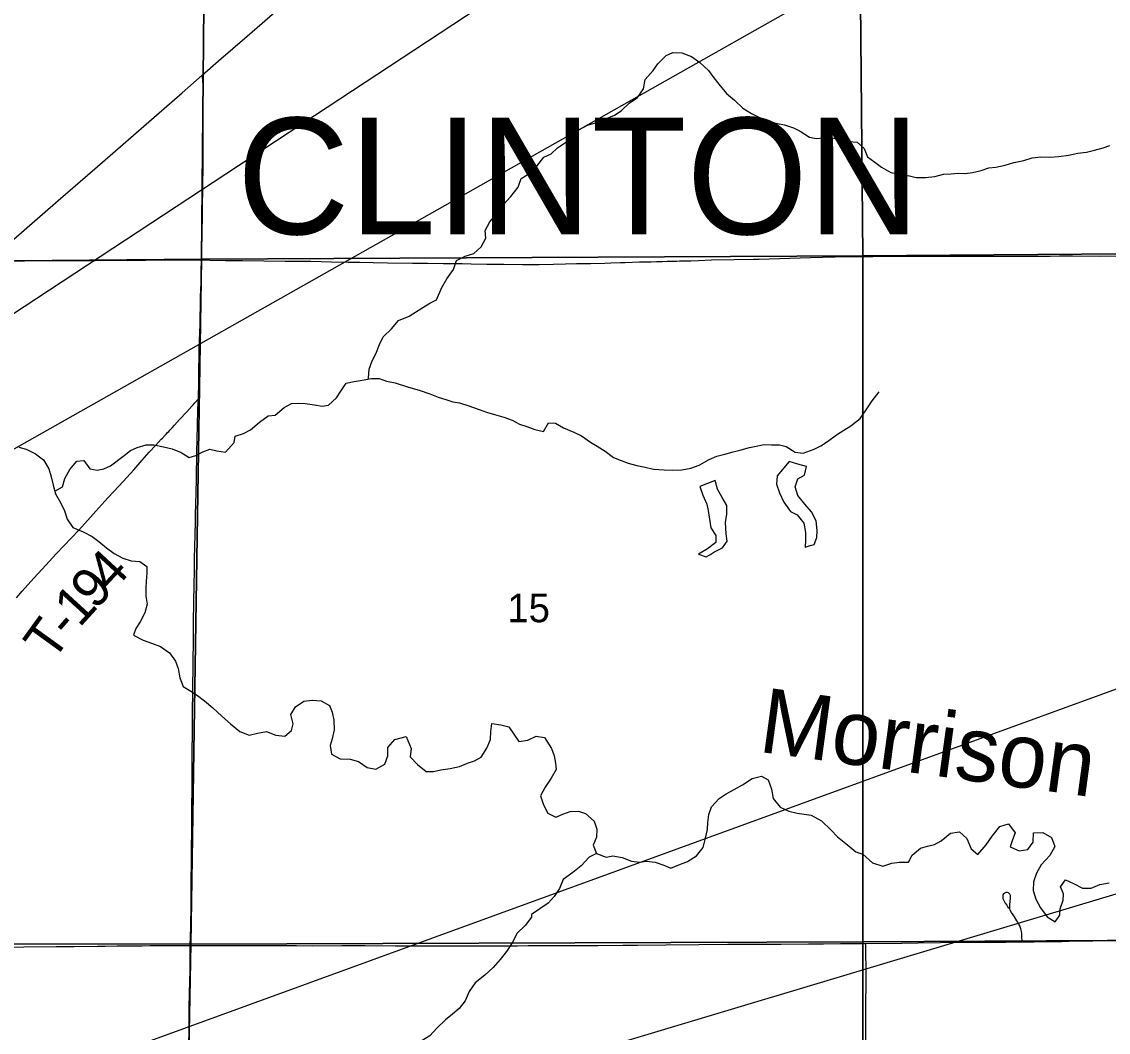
# Model space of a CAD drawing. Extents: x 0 to 34, y 0 to 22.
# Drawn here: x 6.886 to 7.681, y 18.856 to 19.597 of the extents above; entities that cross this region are included whole.
import ezdxf

# ---------------------------------------------------------------- set-up
doc = ezdxf.new("R2010")
doc.units = 0
for name, color, linetype in [('GM_X_Minor_Lake', 7, 'Continuous'), ('GM_X_Minor_River', 7, 'Continuous'), ('GM_X_Minor_River_Text', 7, 'Continuous'), ('GM_X_Section', 7, 'Continuous'), ('GM_X_Section_Text', 7, 'Continuous'), ('GM_X_State_Route', 7, 'Continuous'), ('GM_X_Township_Road', 7, 'Continuous'), ('GM_X_Township_Road_Text', 7, 'Continuous'), ('GM_X_Township_Text', 7, 'Continuous'), ('SH_Text', 7, 'Continuous')]:
    doc.layers.add(name, color=color, linetype=linetype)

msp = doc.modelspace()

# ---------------------------------------------------------------- linework, layer by layer
at = {"layer": 'GM_X_Minor_Lake'}
for points in [[(7.44728, 19.27438), (7.43871, 19.264), (7.43811, 19.25775), (7.44034, 19.25148), (7.44352, 19.24463), (7.4484, 19.23797), (7.4533, 19.23529), (7.45818, 19.22938), (7.45947, 19.22255), (7.45943, 19.21686), (7.45921, 19.21174), (7.46288, 19.21291)], [(7.46288, 19.21291), (7.46566, 19.21379), (7.46777, 19.2189), (7.4678, 19.22383), (7.46727, 19.23104), (7.46371, 19.2375), (7.45883, 19.24322), (7.45376, 19.2495), (7.45171, 19.25596), (7.45383, 19.26183), (7.45857, 19.26446), (7.46012, 19.27071), (7.4537, 19.27245), (7.44728, 19.27438)], [(7.38922, 19.20618), (7.39223, 19.20813), (7.39849, 19.21113), (7.40193, 19.21623), (7.40139, 19.22154), (7.40068, 19.22989), (7.40166, 19.23595), (7.4017, 19.24221), (7.39833, 19.24811), (7.39496, 19.25419), (7.39329, 19.26046), (7.38211, 19.25616)], [(7.38211, 19.25616), (7.38415, 19.2497), (7.38714, 19.24324), (7.38806, 19.23849), (7.38897, 19.23223), (7.39006, 19.22578), (7.39363, 19.22026), (7.3936, 19.21514), (7.38752, 19.21062), (7.38106, 19.20649), (7.38672, 19.20456), (7.38922, 19.20618)]]:
    msp.add_lwpolyline(points, dxfattribs=at)
at = {"layer": 'GM_X_Minor_River'}
for points in [[(7.16914, 19.3808), (7.17914, 19.38719), (7.18445, 19.39038), (7.18919, 19.39282), (7.19303, 19.4019), (7.19685, 19.40814), (7.20162, 19.41513), (7.20393, 19.42156), (7.21019, 19.42475), (7.21663, 19.4268), (7.22195, 19.4317), (7.22521, 19.43794), (7.22486, 19.44363), (7.2283, 19.44987), (7.23306, 19.45553), (7.23802, 19.46233), (7.24354, 19.46856), (7.24888, 19.47535), (7.25119, 19.4816), (7.25745, 19.48555), (7.26278, 19.49083), (7.26773, 19.49725), (7.27304, 19.49987), (7.2778, 19.50421), (7.28502, 19.5091), (7.28976, 19.5121), (7.29339, 19.51739), (7.29984, 19.52077), (7.30647, 19.52263), (7.31254, 19.52506), (7.31955, 19.52806), (7.32449, 19.53125), (7.3302, 19.53691), (7.33646, 19.54105), (7.34066, 19.54747), (7.34203, 19.55429), (7.34774, 19.5607), (7.35117, 19.5658), (7.35745, 19.57184), (7.36219, 19.5739), (7.36881, 19.57367), (7.37598, 19.57098), (7.38201, 19.56658), (7.38822, 19.56086), (7.39216, 19.55553), (7.39592, 19.55076), (7.40155, 19.54391), (7.40739, 19.53913), (7.41341, 19.53322), (7.41981, 19.5292), (7.42566, 19.52633), (7.43132, 19.52383), (7.43756, 19.52228), (7.44398, 19.5211), (7.45059, 19.51879), (7.45549, 19.5163), (7.46228, 19.51209), (7.46719, 19.51111), (7.47287, 19.51146), (7.47778, 19.51143), (7.48383, 19.51083), (7.49101, 19.50889), (7.49725, 19.50829), (7.50233, 19.50371), (7.50475, 19.49763), (7.51003, 19.49362), (7.51511, 19.48999), (7.5219, 19.48616), (7.52833, 19.48479), (7.53551, 19.48362), (7.54042, 19.48245), (7.54723, 19.48241), (7.55404, 19.48313), (7.5603, 19.48499), (7.56597, 19.48515), (7.57089, 19.4855), (7.57619, 19.48547), (7.58168, 19.48601), (7.58793, 19.48769), (7.59362, 19.48955), (7.59873, 19.49009), (7.60554, 19.49157), (7.61199, 19.49343), (7.61918, 19.49491), (7.62525, 19.49696), (7.63168, 19.49768), (7.6383, 19.49745), (7.64493, 19.4978), (7.65193, 19.49871), (7.65875, 19.50018), (7.66518, 19.5011), (7.67087, 19.50239), (7.67731, 19.50406), (7.68224, 19.50593)], [(7.13907, 19.33485), (7.13946, 19.33574), (7.13988, 19.34219), (7.142, 19.34826), (7.14488, 19.35337), (7.14757, 19.36018), (7.15026, 19.36586), (7.15616, 19.37152), (7.16151, 19.37776), (7.16914, 19.3808)], [(6.90975, 19.25273), (6.91548, 19.25581), (6.91703, 19.26207), (6.92067, 19.2685), (6.92601, 19.27473), (6.93094, 19.27508), (6.93545, 19.26898), (6.94074, 19.268), (6.94567, 19.26911), (6.95061, 19.27136), (6.96051, 19.2789), (6.96527, 19.28247), (6.97001, 19.28472), (6.97665, 19.28658), (6.98234, 19.28674), (6.98934, 19.28518), (6.99558, 19.28381), (7.00219, 19.28112), (7.00823, 19.27747), (7.01297, 19.27878), (7.0181, 19.28159), (7.02323, 19.28346), (7.02833, 19.28229), (7.03477, 19.28131), (7.04106, 19.28829), (7.04185, 19.29303), (7.04792, 19.2949), (7.05305, 19.29771), (7.05953, 19.30337), (7.06599, 19.30789), (7.07111, 19.30843), (7.07759, 19.31409), (7.08309, 19.3169), (7.08783, 19.31725), (7.09313, 19.31703), (7.09995, 19.31585), (7.10543, 19.31487), (7.11017, 19.3156), (7.11608, 19.32107), (7.11914, 19.32599), (7.12296, 19.33185), (7.12884, 19.33315), (7.13491, 19.33406), (7.14173, 19.33535), (7.14723, 19.33513), (7.15252, 19.33339), (7.15895, 19.33202), (7.16879, 19.32899)], [(7.16879, 19.32899), (7.17652, 19.32671), (7.18426, 19.32401), (7.19048, 19.3217), (7.19596, 19.31978), (7.20125, 19.31823), (7.20616, 19.31744), (7.21296, 19.31532), (7.22051, 19.31262), (7.22579, 19.31051), (7.23165, 19.30877), (7.23845, 19.30702), (7.24468, 19.30471), (7.24996, 19.30184), (7.25524, 19.3001), (7.26109, 19.2978), (7.26752, 19.29643), (7.27115, 19.30267), (7.27644, 19.30245), (7.28229, 19.2992), (7.28965, 19.29593), (7.2953, 19.29324), (7.3019, 19.28866), (7.3068, 19.28559), (7.31264, 19.28196), (7.31867, 19.27737), (7.32452, 19.27526), (7.32962, 19.27314), (7.33585, 19.27159), (7.3419, 19.27023), (7.34813, 19.26887), (7.35588, 19.26826), (7.36231, 19.26803), (7.36893, 19.26837), (7.37537, 19.26947), (7.38144, 19.2719), (7.38884, 19.27603), (7.39453, 19.27847), (7.40021, 19.27976), (7.40646, 19.28163), (7.41234, 19.28311), (7.4184, 19.28478), (7.42332, 19.2857), (7.4292, 19.287), (7.43449, 19.28678), (7.44035, 19.28656), (7.44527, 19.28539), (7.45167, 19.28137), (7.45753, 19.28058), (7.46568, 19.28357), (7.47062, 19.28582), (7.47555, 19.28921), (7.48201, 19.29391), (7.48733, 19.29748), (7.49246, 19.30068), (7.49948, 19.30595), (7.50368, 19.31237), (7.50807, 19.31879), (7.51322, 19.3254)], [(6.88346, 19.28485), (6.88875, 19.28349), (6.89555, 19.28004), (6.9014, 19.27564), (6.90552, 19.26916), (6.907, 19.26326), (6.90848, 19.25718), (6.91033, 19.25071), (6.91389, 19.24443), (6.91688, 19.23834), (6.91893, 19.23225), (6.92306, 19.22615), (6.93042, 19.22288), (6.93703, 19.21942), (6.94193, 19.21598), (6.94759, 19.2112), (6.95324, 19.20699), (6.95966, 19.20372), (6.96571, 19.20179), (6.97196, 19.20118), (6.97705, 19.19755), (6.97721, 19.1928), (6.9766, 19.18692), (6.97638, 19.18198), (6.97634, 19.17591), (6.97744, 19.17002), (6.9757, 19.16357), (6.97225, 19.15714), (6.969, 19.15222), (6.96745, 19.1473), (6.97444, 19.14365), (6.98048, 19.14133), (6.9871, 19.13902), (6.9937, 19.13442), (6.99802, 19.12813), (7.00007, 19.12299), (7.00135, 19.11615), (7.00377, 19.10968), (7.00943, 19.10623), (7.01434, 19.10298), (7.01943, 19.09915), (7.02546, 19.09399), (7.03205, 19.08787), (7.03845, 19.08233), (7.04523, 19.07679), (7.05204, 19.07409), (7.05811, 19.07557), (7.06474, 19.07667), (7.07155, 19.07416)], [(7.07155, 19.07416), (7.07817, 19.07337), (7.08312, 19.07751), (7.08429, 19.08244), (7.08262, 19.08929), (7.08588, 19.09477), (7.09215, 19.09891), (7.09822, 19.09963), (7.10466, 19.09922), (7.11088, 19.09576), (7.11275, 19.09082), (7.11404, 19.08511), (7.11437, 19.0779), (7.11282, 19.07145), (7.11127, 19.06653), (7.11237, 19.06006), (7.11879, 19.0568), (7.12598, 19.05657), (7.13222, 19.05482), (7.13844, 19.05042), (7.14488, 19.04924), (7.15134, 19.05281), (7.15365, 19.05887), (7.15369, 19.06514), (7.15862, 19.07085), (7.16703, 19.07301)], [(7.16703, 19.07301), (7.17065, 19.0643), (7.16986, 19.05824), (7.17531, 19.05252), (7.18171, 19.04755), (7.18701, 19.04733), (7.19231, 19.04863), (7.19913, 19.04954), (7.20595, 19.05121), (7.21201, 19.05364), (7.21713, 19.05532), (7.22187, 19.05795), (7.22607, 19.06456), (7.22876, 19.07099), (7.22898, 19.07668), (7.22977, 19.08256), (7.2362, 19.08157), (7.24224, 19.08021), (7.24637, 19.07412), (7.24956, 19.06936), (7.25599, 19.07027), (7.26207, 19.07327), (7.2683, 19.07229), (7.27336, 19.0643), (7.27541, 19.05898), (7.27633, 19.05366), (7.27687, 19.04892), (7.27324, 19.04268), (7.26866, 19.03607), (7.26541, 19.02964), (7.26745, 19.02299), (7.27082, 19.01691), (7.27667, 19.01403), (7.28179, 19.01628), (7.28709, 19.01814), (7.29315, 19.01849), (7.29825, 19.01675), (7.30464, 19.01103), (7.30669, 19.00533), (7.30628, 18.99926), (7.30379, 18.9934), (7.3064, 18.98732), (7.31338, 18.98462), (7.31831, 18.98573), (7.32511, 18.98456), (7.3319, 18.98187), (7.33814, 18.98107), (7.34306, 18.9818), (7.3493, 18.98101), (7.35572, 18.97889), (7.36082, 18.97677), (7.36669, 18.97902), (7.37295, 18.98145), (7.3796, 18.98577), (7.38436, 18.99181), (7.3861, 18.99863), (7.38765, 19.00488), (7.38787, 19.01), (7.38866, 19.01606), (7.39058, 19.02155), (7.39611, 19.02759), (7.40123, 19.03116), (7.40711, 19.03416), (7.41319, 19.03773), (7.42021, 19.04243), (7.42703, 19.0441), (7.43194, 19.04142), (7.43436, 19.03439), (7.43564, 19.02755), (7.44071, 19.02127), (7.44713, 19.01839), (7.45336, 19.01703), (7.45846, 19.01624), (7.46338, 19.01545), (7.47111, 19.01124), (7.47807, 19.00437), (7.48277, 18.99961), (7.48898, 18.99464), (7.49632, 18.98853), (7.50123, 18.98699), (7.50838, 18.9805), (7.51594, 18.97818), (7.52257, 18.98042), (7.52787, 18.98115), (7.53468, 18.98111), (7.53736, 18.98622), (7.54363, 18.9913), (7.54856, 18.99279), (7.55386, 18.9939), (7.55879, 18.99672), (7.56545, 19.00218), (7.57207, 19.00328), (7.57753, 18.99832), (7.5807, 18.99072), (7.5856, 18.98671), (7.5915, 18.99369), (7.59589, 19.00011), (7.6016, 19.0071), (7.60805, 19.00915), (7.61293, 19.00248), (7.61101, 18.99737)], [(7.61101, 18.99737), (7.60927, 18.99226), (7.61569, 18.98938), (7.62213, 18.9903), (7.62613, 18.99577), (7.62617, 19.00241), (7.63317, 19.00275), (7.63939, 18.99911), (7.642, 18.99246), (7.63818, 18.98584), (7.6319, 18.97905), (7.62846, 18.973), (7.62615, 18.96676), (7.62611, 18.96031), (7.62797, 18.95404), (7.63134, 18.94758), (7.63622, 18.9411), (7.64206, 18.93728), (7.64549, 18.94219), (7.6459, 18.94693), (7.64802, 18.95317), (7.64823, 18.95791), (7.64599, 18.96305), (7.6498, 18.96814), (7.65565, 18.96546), (7.66206, 18.96201), (7.6685, 18.96197), (7.67475, 18.96478), (7.68176, 18.96588)], [(7.3064, 18.98732), (7.30109, 18.98469), (7.29519, 18.97847), (7.28892, 18.97357), (7.28189, 18.9683), (7.2792, 18.96187), (7.27539, 18.95601), (7.27101, 18.95111), (7.25884, 18.94281)], [(7.25884, 18.94281), (7.25882, 18.94088), (7.25405, 18.93463), (7.24834, 18.92896), (7.2447, 18.92196), (7.2405, 18.91571), (7.23592, 18.90985), (7.23058, 18.9038), (7.22448, 18.89832), (7.21763, 18.89265), (7.21323, 18.88622), (7.21017, 18.87959), (7.20578, 18.87391), (7.20102, 18.86976), (7.19588, 18.86561), (7.1894, 18.85956), (7.18425, 18.85389), (7.17797, 18.84993), (7.17225, 18.84388), (7.16541, 18.83679)]]:
    msp.add_lwpolyline(points, dxfattribs=at)
at = {"layer": 'GM_X_Section'}
for points in [[(6.53817, 19.93156), (7.02187, 19.92598), (7.01728, 19.42257), (6.52479, 19.41836)], [(7.02187, 19.92598), (7.4966, 19.92992), (7.50144, 19.42512), (7.01728, 19.42257)], [(7.4966, 19.92992), (7.96613, 19.92967), (7.98141, 19.42878), (7.50144, 19.42512)], [(7.50144, 19.42512), (7.50124, 18.92259), (7.00934, 18.92111), (7.01728, 19.42257)], [(7.50144, 19.42512), (7.98141, 19.42878), (7.99306, 18.92551), (7.50124, 18.92259)], [(7.01728, 19.42257), (7.00934, 18.92111), (6.51159, 18.92185), (6.52479, 19.41836)], [(7.99306, 18.92551), (7.99816, 18.41923), (7.50153, 18.41698), (7.50124, 18.92259)], [(7.00934, 18.92111), (6.99984, 18.41775), (6.50305, 18.41943), (6.51159, 18.92185)], [(7.50124, 18.92259), (7.50153, 18.41698), (6.99984, 18.41775), (7.00934, 18.92111)]]:
    msp.add_lwpolyline(points, close=True, dxfattribs=at)
at = {"layer": 'GM_X_State_Route'}
for points in [[(6.86621, 19.42565), (6.91225, 19.46555), (6.93904, 19.48874), (6.98618, 19.52975), (7.00311, 19.54438), (7.01772, 19.55727), (7.02968, 19.56783), (7.05049, 19.58605), (7.0745, 19.60676)], [(7.52955, 18.92178), (7.52999, 18.92178), (7.54179, 18.9219), (7.55826, 18.92224), (7.57381, 18.92235), (7.58778, 18.92242), (7.60611, 18.92258), (7.60735, 18.9226), (7.61263, 18.92261), (7.61798, 18.92267), (7.62661, 18.92276), (7.63531, 18.92289), (7.64711, 18.92305), (7.6524, 18.92313), (7.6698, 18.92343), (7.69156, 18.92364)], [(6.85756, 18.91859), (6.88709, 18.91894), (6.9107, 18.91923), (6.92407, 18.91935), (6.94115, 18.91959), (6.94675, 18.91965), (6.95545, 18.91974), (6.96353, 18.91977), (6.97378, 18.91983), (6.97968, 18.9199), (6.99163, 18.92), (7.00051, 18.91998), (7.00897, 18.91996), (7.01045, 18.91995), (7.02413, 18.92006), (7.03501, 18.92008), (7.04309, 18.92003), (7.07137, 18.92001), (7.07821, 18.91997), (7.0866, 18.91993), (7.09809, 18.91989), (7.11985, 18.91999), (7.13695, 18.91994), (7.15901, 18.91989), (7.17642, 18.91988), (7.18605, 18.91982), (7.19475, 18.91979), (7.19754, 18.91979), (7.21555, 18.91978), (7.2199, 18.9198), (7.22735, 18.91986), (7.23885, 18.91984), (7.24227, 18.91984), (7.24848, 18.91989), (7.25625, 18.91992), (7.26495, 18.91997), (7.26961, 18.92001), (7.27521, 18.92002), (7.27863, 18.92002), (7.28546, 18.92), (7.28732, 18.92), (7.29725, 18.92006), (7.3075, 18.92012), (7.32551, 18.92026), (7.33639, 18.92036), (7.35721, 18.9205), (7.38114, 18.92072), (7.40258, 18.92094), (7.41875, 18.92109), (7.44143, 18.92105), (7.46163, 18.92126), (7.47251, 18.92136), (7.48494, 18.92141), (7.48712, 18.92142), (7.4924, 18.92143), (7.50357, 18.92153), (7.52955, 18.92178)]]:
    msp.add_lwpolyline(points, dxfattribs=at)
at = {"layer": 'GM_X_Township_Road'}
for points in [[(7.01715, 19.42204), (7.01721, 19.42384), (7.01725, 19.42694), (7.01737, 19.43004), (7.01745, 19.43346), (7.01754, 19.43749), (7.01761, 19.44153), (7.01769, 19.44526), (7.01779, 19.45116), (7.01786, 19.45396), (7.01791, 19.45924), (7.01802, 19.46452), (7.0181, 19.47042), (7.01825, 19.47943), (7.01838, 19.48751), (7.01844, 19.49435), (7.01848, 19.50149), (7.01846, 19.5136), (7.01843, 19.51827), (7.0184, 19.52324), (7.01837, 19.53194), (7.01838, 19.53816), (7.01837, 19.54406), (7.01831, 19.55057), (7.0182, 19.55302), (7.01811, 19.5539), (7.01772, 19.55727)], [(7.01715, 19.42204), (7.02317, 19.42191), (7.03467, 19.42176), (7.0471, 19.42163), (7.07849, 19.42125), (7.09714, 19.42108), (7.11236, 19.4208), (7.12448, 19.42055), (7.13318, 19.42036), (7.14281, 19.42013), (7.15337, 19.41999), (7.1717, 19.41981), (7.18258, 19.41962), (7.19437, 19.4195), (7.20248, 19.41939), (7.20806, 19.41941), (7.21458, 19.41932), (7.22606, 19.41909), (7.23849, 19.41888), (7.25217, 19.41872), (7.2643, 19.41885), (7.27486, 19.41898), (7.28357, 19.41913), (7.29164, 19.41937), (7.30189, 19.41954), (7.31246, 19.41978), (7.31681, 19.41996), (7.32395, 19.4202), (7.32736, 19.4203), (7.3379, 19.42062), (7.34225, 19.42072), (7.34628, 19.4208), (7.35032, 19.42088), (7.35436, 19.42098), (7.35808, 19.42108), (7.36149, 19.42118), (7.36521, 19.42129), (7.36706, 19.42134), (7.36954, 19.42141), (7.3717, 19.42145), (7.37541, 19.42152), (7.38099, 19.42175), (7.3906, 19.42207), (7.40707, 19.42243), (7.42136, 19.42269), (7.4254, 19.42275), (7.43286, 19.42293), (7.44032, 19.42316), (7.463, 19.42376), (7.47169, 19.42402), (7.48101, 19.42425), (7.49126, 19.42451), (7.50089, 19.42464), (7.50524, 19.42468), (7.50866, 19.42471), (7.51301, 19.42475), (7.52016, 19.42483), (7.52699, 19.42489), (7.53228, 19.42491), (7.53663, 19.4249), (7.55527, 19.4249), (7.56024, 19.42488), (7.56553, 19.42485), (7.57672, 19.42482), (7.59008, 19.42483), (7.59972, 19.42485), (7.60562, 19.42486), (7.61059, 19.42489), (7.61463, 19.4249), (7.61991, 19.42492), (7.62768, 19.42495), (7.63856, 19.42494), (7.64539, 19.42498), (7.64943, 19.42499), (7.65471, 19.425), (7.6746, 19.42492), (7.69543, 19.42502)], [(6.86138, 19.42139), (6.87402, 19.42147), (6.8877, 19.42152), (6.89857, 19.42162), (6.90789, 19.42169), (6.92467, 19.42177), (6.92746, 19.42174), (6.92995, 19.42175), (6.93927, 19.42178), (6.95481, 19.42184), (6.96787, 19.42188), (6.97626, 19.42198), (6.99086, 19.42216), (6.99987, 19.42217), (7.00981, 19.42216), (7.01602, 19.42207), (7.01715, 19.42204)], [(7.01488, 19.32025), (7.0151, 19.33308), (7.01512, 19.33396), (7.01514, 19.33547), (7.01521, 19.34009), (7.01527, 19.3438), (7.01541, 19.34908), (7.01548, 19.35218), (7.01557, 19.35653), (7.01591, 19.36895), (7.01609, 19.37485), (7.01619, 19.3795), (7.01625, 19.38229), (7.01628, 19.38322), (7.01634, 19.38538), (7.01637, 19.38755), (7.01642, 19.39003), (7.01645, 19.39189), (7.01647, 19.39375), (7.01652, 19.39623), (7.0166, 19.39902), (7.01681, 19.40679), (7.01689, 19.41144), (7.01701, 19.41672), (7.01707, 19.4192), (7.01713, 19.42168), (7.01715, 19.42204)], [(6.88164, 19.17457), (6.88585, 19.17954), (6.89433, 19.18904), (6.9005, 19.1956), (6.91084, 19.20687), (6.92197, 19.21849), (6.92714, 19.224), (6.93397, 19.2315), (6.93976, 19.238), (6.94643, 19.24537), (6.94896, 19.24811), (6.9566, 19.25633), (6.96254, 19.26278), (6.96761, 19.26845), (6.97366, 19.27534), (6.97895, 19.28123), (6.9837, 19.28638), (6.98773, 19.2908), (6.98854, 19.29161), (6.99067, 19.29382), (6.99131, 19.29449), (6.99238, 19.2956), (6.99322, 19.29651), (6.99409, 19.29739), (6.99491, 19.29831), (6.99577, 19.29922), (6.99742, 19.30106), (7.00111, 19.30523), (7.00633, 19.31093), (7.0101, 19.31499), (7.01111, 19.31607), (7.0124, 19.3175), (7.01488, 19.32025)], [(7.00897, 18.91996), (7.00929, 18.93358), (7.00939, 18.93914), (7.0095, 18.9444), (7.00952, 18.94718), (7.00955, 18.94873), (7.00955, 18.95182), (7.00958, 18.95337), (7.00958, 18.95615), (7.0096, 18.95832), (7.00963, 18.96173), (7.00972, 18.97134), (7.00978, 18.97724), (7.00979, 18.97942), (7.00988, 18.9909), (7.00993, 18.9968), (7.00997, 18.99804), (7.00997, 19.00207), (7.01004, 19.00455), (7.01006, 19.00889), (7.01012, 19.01075), (7.01011, 19.0154), (7.01015, 19.01695), (7.01014, 19.01974), (7.01019, 19.02253), (7.0102, 19.02346), (7.01021, 19.02686), (7.01026, 19.02934), (7.01023, 19.03212), (7.0104, 19.03767), (7.01043, 19.04383), (7.0104, 19.04754), (7.01037, 19.0559), (7.01042, 19.06459), (7.01047, 19.07298), (7.01057, 19.08417), (7.01066, 19.09349), (7.01077, 19.10312), (7.01092, 19.1143), (7.011, 19.11895), (7.01117, 19.13071), (7.0112, 19.14025), (7.01128, 19.14652), (7.01136, 19.15553), (7.01161, 19.17232), (7.01199, 19.19469), (7.01215, 19.20308), (7.01253, 19.22111), (7.01273, 19.23011), (7.01285, 19.23632), (7.01294, 19.24258), (7.01321, 19.25255), (7.01343, 19.26075), (7.01349, 19.26769), (7.0137, 19.2754), (7.01387, 19.28174), (7.01408, 19.29066), (7.0146, 19.31174), (7.01484, 19.31794), (7.01488, 19.32025)], [(7.61798, 18.92267), (7.61783, 18.92708), (7.6178, 18.92794), (7.61767, 18.92888), (7.61747, 18.93019), (7.61696, 18.93218), (7.61616, 18.93437), (7.61553, 18.93573), (7.61474, 18.93709), (7.61401, 18.93819), (7.6123, 18.94093), (7.61128, 18.94245), (7.61017, 18.94429), (7.60912, 18.94596), (7.6089, 18.94697), (7.60886, 18.94786), (7.60898, 18.9498), (7.60941, 18.95501), (7.60946, 18.9556), (7.60943, 18.95626), (7.60935, 18.9567), (7.60921, 18.95716), (7.60893, 18.95769), (7.60853, 18.95815), (7.60803, 18.9585), (7.60715, 18.9588), (7.60653, 18.95883), (7.60592, 18.95874), (7.60507, 18.95837), (7.6047, 18.95811), (7.60438, 18.95776), (7.60392, 18.95711), (7.60376, 18.95654), (7.60372, 18.95609), (7.60374, 18.95548), (7.60392, 18.95456), (7.60436, 18.95339), (7.60564, 18.9511), (7.60664, 18.94948), (7.60759, 18.94813), (7.6085, 18.94729)], [(7.00681, 18.78586), (7.00695, 18.79538), (7.00759, 18.82491), (7.0081, 18.8619), (7.00823, 18.87433), (7.00839, 18.8849), (7.00865, 18.89391), (7.0088, 18.90167), (7.00886, 18.91162), (7.00895, 18.91776), (7.00897, 18.91996)], [(7.50354, 18.85039), (7.50356, 18.85877), (7.5036, 18.88084), (7.50366, 18.88861), (7.50365, 18.90415), (7.50364, 18.91378), (7.50361, 18.9172), (7.50357, 18.92153)]]:
    msp.add_lwpolyline(points, dxfattribs=at)
at = {"layer": 'SH_Text'}
for points in [[(9.73806, 20.89938), (5.80799, 18.67786), (9.73806, 21.2643)], [(9.91391, 19.62604), (5.3499, 18.25689), (9.91668, 19.92045)]]:
    msp.add_lwpolyline(points, close=True, dxfattribs=at)

# ---------------------------------------------------------------- texts
at = {"layer": 'GM_X_Minor_River_Text'}
msp.add_text('Morrison', height=0.047369, rotation=352.24064, dxfattribs=at).set_placement((7.42409, 19.06201))
at = {"layer": 'GM_X_Section_Text'}
msp.add_text('15', height=0.020928, rotation=0.00001, dxfattribs=at).set_placement((7.24111, 19.15675))
at = {"layer": 'GM_X_Township_Road_Text'}
for s, rotation, p in [('4', 47.13229, (6.95131, 19.17781)), ('9', 47.16413, (6.93951, 19.16508)), ('1', 47.52672, (6.92782, 19.15231)), ('T', 54.12901, (6.90832, 19.12709)), ('-', 48.83169, (6.92032, 19.14373))]:
    msp.add_text(s, height=0.02841, rotation=rotation, dxfattribs=at).set_placement(p)
at = {"layer": 'GM_X_Township_Text'}
msp.add_text('CLINTON', height=0.085227, rotation=0.00001, dxfattribs=at).set_placement((7.04309, 19.44092))

doc.saveas('drawing.dxf')
